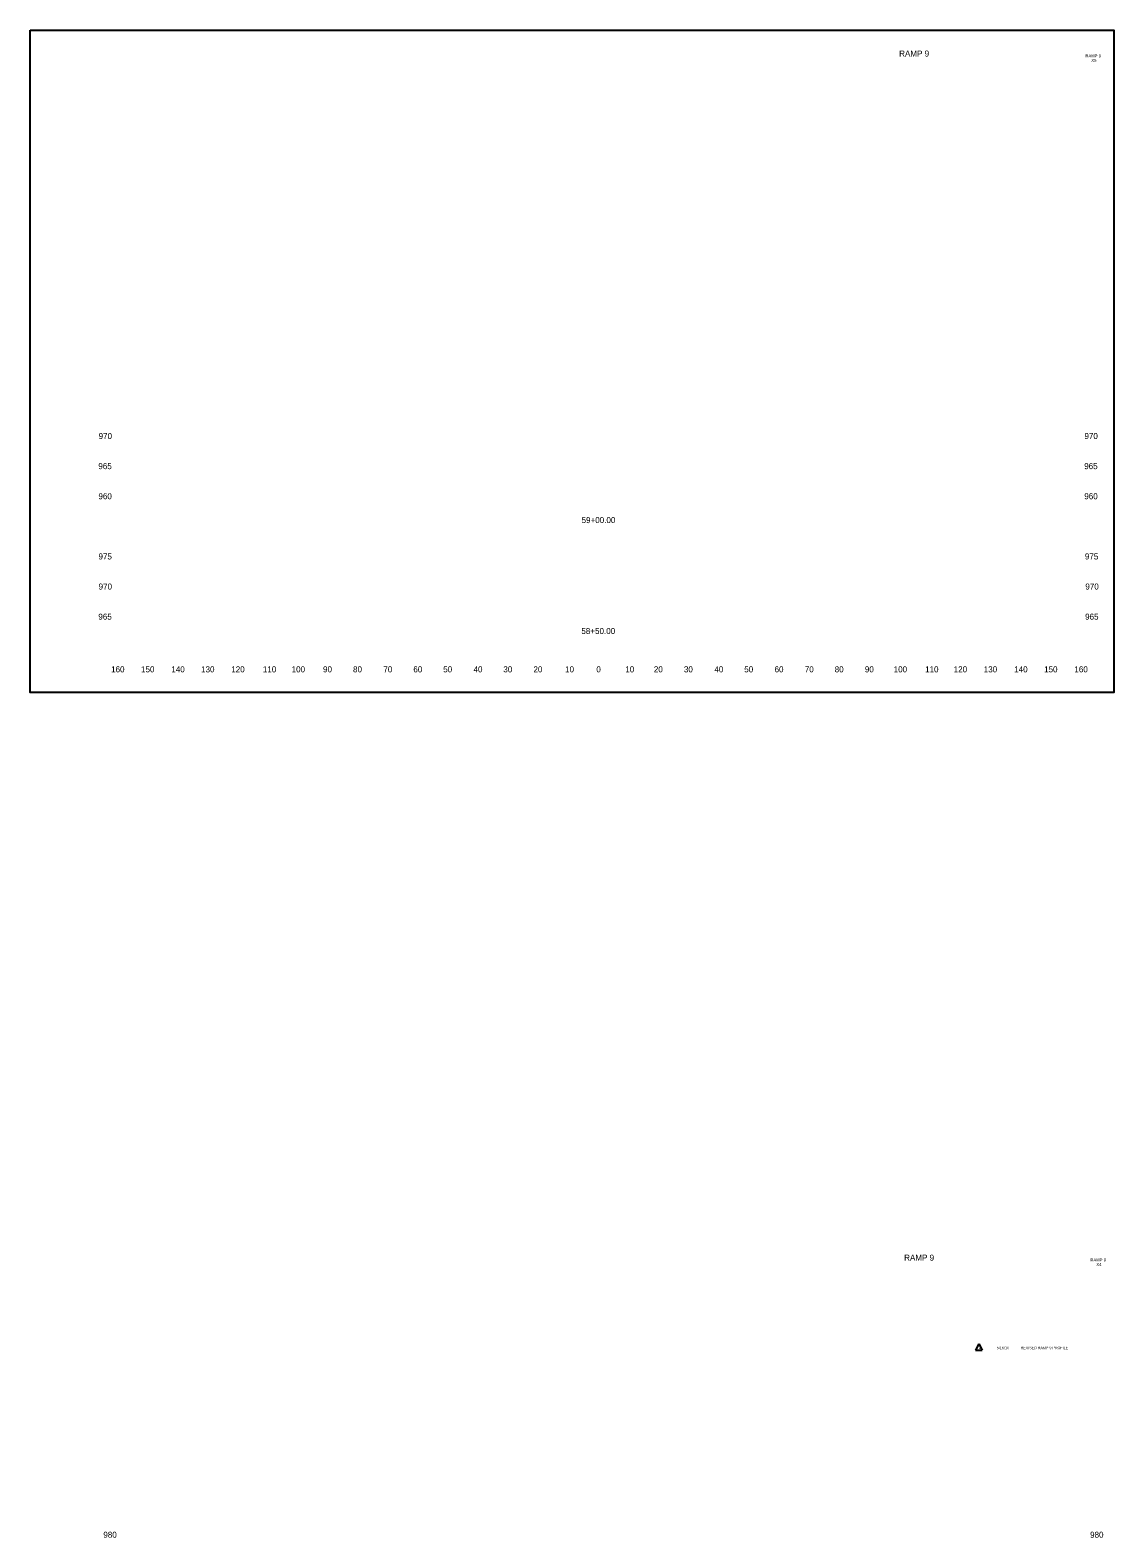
# Model space of a CAD drawing. Extents: x 4970 to 5331, y 4591 to 6811.
# Drawn here: x 4970 to 5330, y 6310 to 6811 of the extents above; entities that cross this region are included whole.
import ezdxf

# ---------------------------------------------------------------- set-up
doc = ezdxf.new("R2010")
doc.units = 0
for name, color, linetype in [('RD_SHT_ID', 7, 'Continuous'), ('RD_SHT_IplotShp', 7, 'Continuous'), ('RD_SHT_TX', 7, 'Continuous'), ('RD_XS_TX_Offset', 7, 'Continuous'), ('RD_XS_TX_Station', 7, 'Continuous')]:
    doc.layers.add(name, color=color, linetype=linetype)

msp = doc.modelspace()

# ---------------------------------------------------------------- linework, layer by layer
at = {"layer": 'RD_SHT_IplotShp'}
msp.add_lwpolyline([(4969.55, 6810.84), (5329.55, 6810.84), (5329.55, 6590.84), (4969.55, 6590.84)], close=True, dxfattribs=at)
at = {"layer": 'RD_SHT_TX'}
for p, q in [((5284.71, 6374.39), (5283.57, 6372.36)), ((5283.57, 6372.36), (5285.85, 6372.36)), ((5284.71, 6374.39), (5285.85, 6372.36))]:
    msp.add_line(p, q, dxfattribs=at)

# ---------------------------------------------------------------- texts
at = {"layer": 'RD_SHT_ID'}
for s, height, p in [('RAMP 9', 2, (5258.23, 6802.06)), ('RAMP 9', 1, (5320.12, 6801.8)), ('X5', 1, (5322.08, 6800.3)), ('RAMP 9', 2, (5259.89, 6402.06)), ('RAMP 9', 1, (5321.78, 6401.8)), ('X4', 1, (5323.74, 6400.3))]:
    msp.add_text(s, height=height, dxfattribs=at).set_placement(p)
at = {"layer": 'RD_SHT_TX'}
for s, p in [('1', (5284.71, 6372.69)), ('5/16/16', (5290.67, 6372.65)), ('REVISED RAMP 9 PROFILE', (5298.62, 6372.65))]:
    msp.add_text(s, height=0.88, dxfattribs=at).set_placement(p)
at = {"layer": 'RD_XS_TX_Offset'}
for s, p in [('970', (4992.28, 6675)), ('970', (5319.78, 6675)), ('965', (4992.2, 6665)), ('965', (5319.7, 6665)), ('960', (4992.23, 6655)), ('960', (5319.73, 6655)), ('975', (4992.25, 6635)), ('975', (5319.93, 6635)), ('970', (4992.28, 6625)), ('970', (5320.08, 6625)), ('965', (4992.2, 6615)), ('965', (5320, 6615)), ('160', (4996.44, 6597.5)), ('150', (5006.38, 6597.5)), ('140', (5016.44, 6597.5)), ('130', (5026.33, 6597.5)), ('120', (5036.35, 6597.5)), ('110', (5046.85, 6597.5)), ('100', (5056.41, 6597.5)), ('90', (5066.84, 6597.5)), ('80', (5076.81, 6597.5)), ('70', (5086.88, 6597.5)), ('60', (5096.84, 6597.5)), ('50', (5106.77, 6597.5)), ('40', (5116.84, 6597.5)), ('30', (5126.73, 6597.5)), ('20', (5136.74, 6597.5)), ('10', (5147.25, 6597.5)), ('0', (5157.64, 6597.5)), ('0', (5157.64, 6597.5)), ('10', (5167.25, 6597.5)), ('20', (5176.74, 6597.5)), ('30', (5186.73, 6597.5)), ('40', (5196.84, 6597.5)), ('50', (5206.77, 6597.5)), ('60', (5216.84, 6597.5)), ('70', (5226.88, 6597.5)), ('80', (5236.81, 6597.5)), ('90', (5246.84, 6597.5)), ('100', (5256.41, 6597.5)), ('110', (5266.85, 6597.5)), ('120', (5276.35, 6597.5)), ('130', (5286.33, 6597.5)), ('140', (5296.44, 6597.5)), ('150', (5306.38, 6597.5)), ('160', (5316.44, 6597.5)), ('980', (4993.86, 6310)), ('980', (5321.66, 6310))]:
    msp.add_text(s, height=2, dxfattribs=at).set_placement(p)
at = {"layer": 'RD_XS_TX_Station'}
for s, p in [('59+00.00', (5152.73, 6647.08)), ('58+50.00', (5152.66, 6610.22))]:
    msp.add_text(s, height=2, dxfattribs=at).set_placement(p)

doc.saveas('drawing.dxf')
